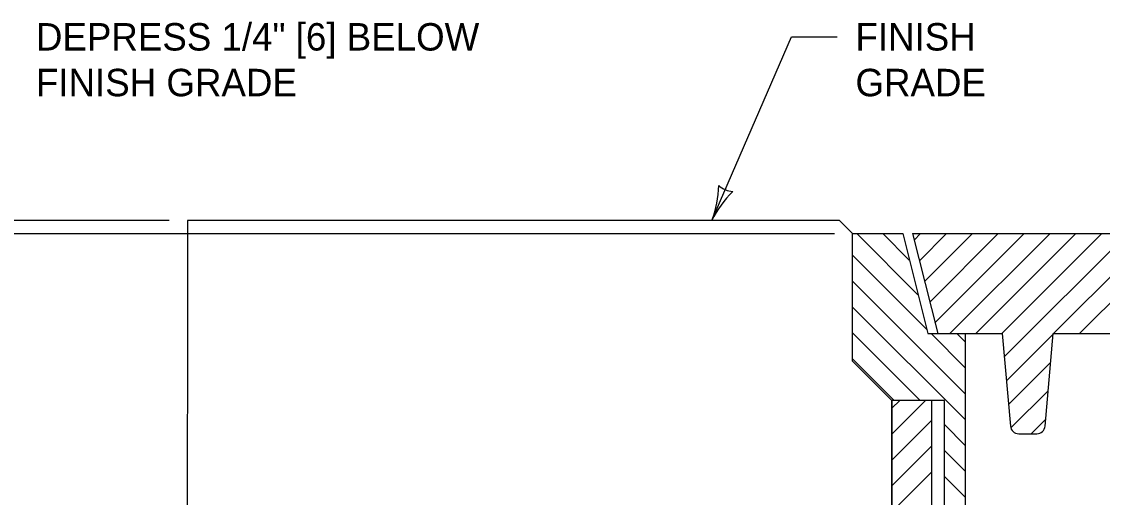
# Model space of a CAD drawing. Extents: x 49991.4 to 50021, y 49987.6 to 50011.4.
# Drawn here: x 50000.755 to 50003.118, y 49996.19 to 49997.23 of the extents above; entities that cross this region are included whole.
import ezdxf

# ---------------------------------------------------------------- set-up
doc = ezdxf.new("R2010")
doc.units = 0
for name, color, linetype in [('Level 1', 7, 'Continuous'), ('Level 2', 7, 'Continuous'), ('Level 3', 7, 'Continuous')]:
    doc.layers.add(name, color=color, linetype=linetype)

msp = doc.modelspace()

# ---------------------------------------------------------------- linework, layer by layer
at = {"layer": 'Level 1'}
for p, q in [((50002.5434, 49996.7952), (50001.1179, 49996.7952)), ((50002.5721, 49996.7665), (50002.5434, 49996.7952)), ((50002.5721, 49996.4875), (50002.5721, 49996.7665)), ((50002.5721, 49996.7665), (50002.6815, 49996.7665)), ((50002.5813, 49996.7665), (50002.7149, 49996.6329)), ((50002.6379, 49996.7665), (50002.696, 49996.7083)), ((50002.6815, 49996.7665), (50002.7362, 49996.5477)), ((50002.7033, 49996.7665), (50002.758, 49996.5477)), ((50002.7033, 49996.7665), (50003.3013, 49996.7665)), ((50002.7068, 49996.7525), (50002.7208, 49996.7665)), ((50002.7181, 49996.7072), (50002.7774, 49996.7665)), ((50002.7295, 49996.662), (50002.834, 49996.7665)), ((50002.7408, 49996.6167), (50002.8905, 49996.7665)), ((50002.7521, 49996.5714), (50002.9471, 49996.7665)), ((50002.7849, 49996.5477), (50003.0037, 49996.7665)), ((50002.8415, 49996.5477), (50003.0602, 49996.7665)), ((50002.8981, 49996.5477), (50003.1168, 49996.7665)), ((50002.9037, 49996.4968), (50003.1734, 49996.7665)), ((50003.0112, 49996.5477), (50003.2299, 49996.7665)), ((50003.0678, 49996.5477), (50003.2865, 49996.7665)), ((50002.5721, 49996.7191), (50002.7337, 49996.5575)), ((50002.5721, 49996.6625), (50002.8182, 49996.4164)), ((50002.5721, 49996.6059), (50002.8182, 49996.3599)), ((50002.5721, 49996.5494), (50002.7196, 49996.4019)), ((50002.7362, 49996.5477), (50002.8182, 49996.5477)), ((50002.7435, 49996.5477), (50002.8182, 49996.473)), ((50002.8001, 49996.5477), (50002.8182, 49996.5296)), ((50002.8182, 49996.5477), (50002.8993, 49996.5477)), ((50002.8182, 49996.5477), (50002.8182, 49995.2352)), ((50002.8993, 49996.5477), (50002.917, 49996.3456)), ((50002.9083, 49996.4448), (50003.0104, 49996.5469)), ((50002.9928, 49996.3456), (50003.0105, 49996.5477)), ((50003.0105, 49996.5477), (50003.2457, 49996.5477)), ((50002.5721, 49996.4928), (50002.6631, 49996.4019)), ((50002.6577, 49996.4019), (50002.5721, 49996.4875)), ((50002.9128, 49996.3928), (50003.005, 49996.4849)), ((50002.9182, 49996.3416), (50002.9996, 49996.423)), ((50002.6577, 49996.4019), (50002.6577, 49995.0529)), ((50002.6577, 49996.3845), (50002.6751, 49996.4019)), ((50002.6577, 49996.328), (50002.7316, 49996.4019)), ((50002.7307, 49996.4019), (50002.6577, 49996.4019)), ((50002.7726, 49996.4019), (50002.7307, 49996.4019)), ((50002.7453, 49994.98), (50002.7453, 49996.4019)), ((50002.7726, 49995.2352), (50002.7726, 49996.4019)), ((50002.6577, 49996.2714), (50002.7453, 49996.3589)), ((50002.7726, 49996.3489), (50002.8182, 49996.3033)), ((50002.9621, 49996.329), (50002.9941, 49996.361)), ((50002.9351, 49996.329), (50002.9747, 49996.329)), ((50002.6577, 49996.2148), (50002.7453, 49996.3024)), ((50002.7726, 49996.2923), (50002.8182, 49996.2467)), ((50002.6577, 49996.1583), (50002.7453, 49996.2458)), ((50002.7726, 49996.2357), (50002.8182, 49996.1901))]:
    msp.add_line(p, q, dxfattribs=at)
for points in [[(50002.6577, 49996.1583), (50002.6577, 49996.2148), (50002.6577, 49996.2714), (50002.6577, 49996.328), (50002.6577, 49996.3845), (50002.6577, 49996.4019), (50002.5721, 49996.4875), (50002.5721, 49996.5494), (50002.5721, 49996.6059), (50002.5721, 49996.6625), (50002.5721, 49996.7191), (50002.5721, 49996.7665), (50002.5434, 49996.7952), (50002.0616, 49996.7952), (50001.1179, 49996.7952), (50001.1179, 49996.7665)], [(50001.1179, 49996.7665), (50001.1174, 49995.9778)]]:
    msp.add_lwpolyline(points, dxfattribs=at)
for centre, start, end in [((50002.9351, 49996.3472), 185, 270), ((50002.9747, 49996.3472), 270, 355)]:
    msp.add_arc(centre, 0.0182, start, end, dxfattribs=at)
at = {"layer": 'Level 3'}
for p, q in [((50002.2644, 49996.7952), (50002.4383, 49997.197)), ((50002.4382, 49997.1968), (50002.5382, 49997.1968)), ((50001.0779, 49996.7952), (50000.5464, 49996.7952)), ((50000.5464, 49996.7665), (50002.5321, 49996.7665))]:
    msp.add_line(p, q, dxfattribs=at)
for centre, radius, start, end in [((50002.0463, 49996.8771), 0.233, 339.4273, 358.6771), ((50002.3153, 49996.9129), 0.0548, 228.7388, 264.4612), ((50002.4646, 49996.6986), 0.2223, 134.056, 154.2395)]:
    msp.add_arc(centre, radius, start, end, dxfattribs=at)

# ---------------------------------------------------------------- texts
at = {"layer": 'Level 2'}
for s, p in [('DEPRESS 1/4" [6] BELOW', (50000.7864, 49997.1668)), ('FINISH', (50002.5782, 49997.1668)), ('FINISH GRADE', (50000.7864, 49997.0668)), ('GRADE', (50002.5782, 49997.0668))]:
    msp.add_text(s, height=0.06, dxfattribs=at).set_placement(p)

doc.saveas('drawing.dxf')
